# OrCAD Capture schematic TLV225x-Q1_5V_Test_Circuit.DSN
size A; title: TLV225x-Q1, TLV225xA-Q1 Advanced LinCMOS RAIL-TO-RAIL; rev: 1.1; note: Datasheet: SGLS192B EVM: N/A
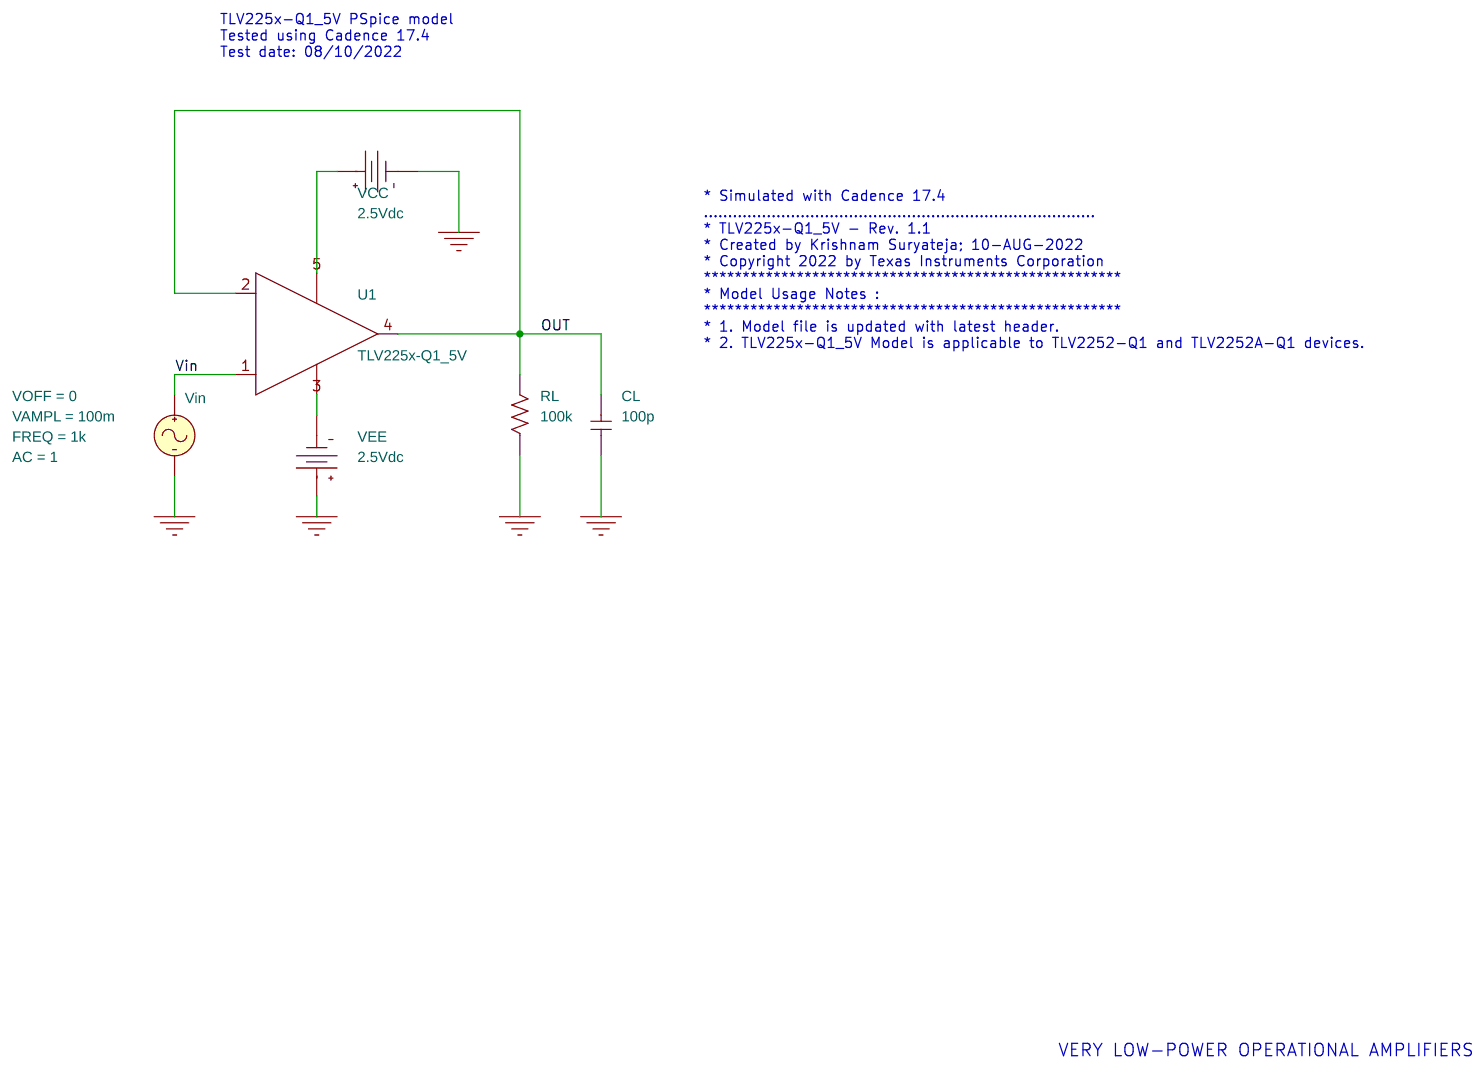
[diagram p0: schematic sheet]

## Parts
CL  100p  [RAD/CK05]
RL  100k  [AX/RC05]
U1  TLV225x-Q1_5V
VCC  VDC
VEE  VDC
Vin  VSIN

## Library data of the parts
CL = C
RL = R
U1 = TLV225x-Q1_5V
VCC VEE = VDC: DC: 2.5Vdc
Vin = VSIN: AC: 1; FREQ: 1k; VAMPL: 100m; VOFF: 0

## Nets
Vin: U1.1(+) Vin.1(+)
0: CL.1 RL.1 VCC.1(-) VEE.0(+) Vin.2(-)
OUT: CL.2 RL.2 U1.2(-) U1.4(OUT)
N22995: U1.5(V+) VCC.0(+)
N23017: U1.3(V-) VEE.1(-)

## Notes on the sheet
- TLV225x-Q1_5V PSpice model
  Tested using Cadence 17.4
  Test date: 08/10/2022
- * Simulated with Cadence 17.4
  .................................................................................
  * TLV225x-Q1_5V - Rev. 1.1
  * Created by Krishnam Suryateja; 10-AUG-2022
  * Copyright 2022 by Texas Instruments Corporation
  ******************************************************
  * Model Usage Notes :
  ******************************************************
  * 1. Model file is updated with latest header.
  * 2. TLV225x-Q1_5V Model is applicable to TLV2252-Q1 and TLV2252A-Q1 devices.
- VERY LOW-POWER OPERATIONAL AMPLIFIERS
